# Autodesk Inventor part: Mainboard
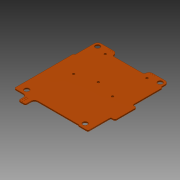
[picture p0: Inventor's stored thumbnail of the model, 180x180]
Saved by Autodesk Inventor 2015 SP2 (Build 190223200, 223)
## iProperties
Created: 2012-08
Part Number: Mainboard
Material: Phenolharz
Document SubType Name: Modeling
Designer: rYan
Mass: 25.8477 g
Surface Area: 244.162 cm^2
Volume: 18.7302 cm^3
Density: 1.38 g/cm^3
Appearance: Glatt - hellorange
Author: rYan
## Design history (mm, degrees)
sketch "Skizze1"
  geometry: L1 (0, 83.325)-(0, -100.704) reference; L2 (-75.98, 0)-(81.98, 0) reference; L3 (-20, -61)-(39, -61); L4 (-25, -66)-(-25, -72); L5 (-27, -74)-(-33, -74); L6 (-35, -72)-(-35, -67); L7 (-40, -62)-(-51, -62); L8 (-53, -60)-(-53, 22); L9 (53, -60)-(53, -31); L10 (55, -29)-(57, -29); L11 (59, -27)-(59, 0); L12 (57, 2)-(55, 2); L13 (53, 4)-(53, 44); L14 (51, 46)-(51, 51); L15 (46, 56)-(28, 56); L16 (21, 49)-(-21, 49); L17 (-51, 24)-(-51, 51); L18 (-46, 56)-(-28, 56); L19 (40, -62)-(51, -62); A1 r 5 centre (-20, -66) between (-20, -61) and (-25, -66); A2 r 2 centre (-27, -72) between (-27, -74) and (-25, -72); A3 r 2 centre (-33, -72) between (-35, -72) and (-33, -74); A4 r 5 centre (-40, -67) between (-35, -67) and (-40, -62); A5 r 2 centre (-51, -60) between (-53, -60) and (-51, -62); A6 r 2 centre (55, -31) between (55, -29) and (53, -31); A7 r 2 centre (57, -27) between (57, -29) and (59, -27); A8 r 2 centre (57, 0) between (59, 0) and (57, 2); A9 r 2 centre (55, 4) between (53, 4) and (55, 2); A10 r 1 centre (52, 44) between (53, 44) and (52, 45); A11 r 1 centre (52, 46) between (51, 46) and (52, 45); A12 r 5 centre (46, 51) between (51, 51) and (46, 56); A13 r 5 centre (28, 51) between (28, 56) and (23, 51); A14 r 2 centre (21, 51) between (21, 49) and (23, 51); A15 r 1 centre (-52, 22) between (-52, 23) and (-53, 22); A16 r 1 centre (-52, 24) between (-52, 23) and (-51, 24); A17 r 5 centre (-46, 51) between (-46, 56) and (-51, 51); A18 r 5 centre (-28, 51) between (-23, 51) and (-28, 56); A19 r 2 centre (-21, 51) between (-23, 51) and (-21, 49); A20 r 0.5 centre (39, -61.5) between (39.5, -61.5) and (39, -61); A21 r 0.5 centre (40, -61.5) between (39.5, -61.5) and (40, -62); A22 r 2 centre (51, -60) between (51, -62) and (53, -60); 1 further point
  constraints: 44 point on circle, 34 end point, 34 tangent, 22 centre point, 9 horizontal, 8 vertical
  dimensions: "d98" = 61 distance between parallel lines of L2 L3; "d99" = 39 distance from line of L3.end L1; "d100" = 20 distance from line of L3.start L1; "d101" = 90 deg dimension on A1.centre L4.start L3.start; "d102" = 5 radius of A1; "d103" = 6 distance of L4.start L4.end; "d104" = 90 deg dimension on A2.centre L5.start L4.end; "d105" = 2 radius of A2; "d106" = 6 distance of L5.start L5.end; "d107" = 90 deg dimension on A3.centre L6.start L5.end; "d108" = 2 radius of A3; "d109" = 5 distance of L6.start L6.end; "d110" = 90 deg dimension on A4.centre L7.start L6.end; "d111" = 5 radius of A4; "d119" = 90 deg dimension on A5.centre L8.start L7.end; "d120" = 2 radius of A5; "d131" = 2 distance of L10.start L10.end; "d132" = 27 distance of L11.start L11.end; "d133" = 2 distance of L12.start L12.end; "d134" = 40 distance of L13.start L13.end; "d135" = 2 radius of A6; "d136" = 2 radius of A9; "d137" = 2 radius of A8; "d138" = 2 radius of A7; "d139" = 5 distance of L14.start L14.end; "d140" = 1 radius of A10; "d141" = 1 radius of A11; "d142" = 0 horizontal distance of A10.centre A11.centre; "d144" = 5 radius of A12; "d145" = 5 radius of A13; "d146" = 90 deg dimension on A13.centre L15.end A13.end; "d148" = 2 radius of A14; "d149" = 1 radius of A15; "d150" = 1 radius of A16; "d151" = 0 horizontal distance of A15.centre A16.centre; "d155" = 5 radius of A17; "d156" = 5 radius of A18; "d184" = 0.5 radius of A20; "d185" = 0.5 radius of A21; "d186" = 1 distance between parallel lines of L19 L3; "d187" = 59 distance between parallel lines of L11 L1; "d188" = 2 distance between parallel lines of L12 L2; "d189" = 2 radius of A22; "d190" = 53 distance between parallel lines of L1 L8; "d191" = 23 distance from line of L2 A15.start; "d192" = 56 distance between parallel lines of L2 L18; "d193" = 2 radius of A19; "d194" = 18 distance of L15.start L15.end; "d195" = 18 distance of L18.start L18.end
extrude "Extrusion1" new body sketch "Skizze1" distance "d11" = 1.6; taper "d12" = 0 deg
sketch "Skizze2"
  geometry: L1 (0, 82)-(0, -100) reference; L2 (-75.4, 0)-(81.4, 0) reference; 4 further points
  constraints: 2 symmetric about line
  dimensions: "d88" = 42 distance from line of L1 point (-42, -55) (= d78); "d89" = 55 distance from line of L2 point (-42, -55) (computed from d79); "d90" = 50 distance from line of L2 point (-45, 50); "d91" = 45 distance from line of L1 point (-45, 50)
hole "Bohrung1" sketch "Skizze2" at (-42, -55), (42, -55), (-45, 50), (45, 50) diameter "d15" = 7; stored, may be unused: countersink angle "d19" = 90 deg, drill point angle "d21" = 118 deg; dims "d16" = 6, "d17" = 4, "d18" = 2, "d20" = 8
sketch "Skizze5"
  geometry: L1 (0, 55.52)-(0, -11.12) reference; L2 (-42, 0)-(42, 0) reference; L3 (-30, 46)-(30, 46); L4 (-28, -1.6)-(28, -1.6); 4 further points
  constraints: 4 end point, 2 coincident, 2 symmetric about line, 1 horizontal, 1 parallel, 1 point on line
  dimensions: "d157" = 6 distance from line of L2 point (0, 6); "d158" = 60 distance of L3.start L3.end; "d159" = 46 distance between parallel lines of L2 L3; "d167" = 56 distance of L4.start L4.end; "d168" = 1.6 distance between parallel lines of L2 L4
hole "Bohrung4" sketch "Skizze5" at (0, 6), (30, 46), (-30, 46), (28, -1.6), (-28, -1.6) diameter "d160" = 3.2; stored, may be unused: countersink angle "d164" = 90 deg, drill point angle "d166" = 118 deg; dims "d161" = 6, "d162" = 4, "d163" = 2, "d165" = 8
sketch "Skizze7"
  geometry: L1 (0, 82)-(0, -100) reference; L2 (-75.4, 0)-(81.4, 0) reference; 2 further points
  dimensions: "d169" = 64.8 distance from line of point (-33.35, -64.8) L2; "d170" = 33.35 distance from line of L1 point (-33.35, -64.8)
hole "Bohrung5" sketch "Skizze7" at (-33.35, -64.8) diameter "d171" = 0.8; stored, may be unused: countersink angle "d175" = 90 deg, drill point angle "d177" = 118 deg; dims "d172" = 6, "d173" = 4, "d174" = 2, "d176" = 8
pattern_linear "Rechteckige Anordnung2" dims "d180" = 2.54, "d183" = 2.54
sketch "Skizze8"
  geometry: L1 (-32.54, 54)-(-27.46, 54); L2 (0, 82)-(0, -100) reference; L3 (-75.4, 0)-(81.4, 0) reference; 2 further points
  constraints: 2 end point, 1 horizontal, 1 midpoint
  dimensions: "d196" = 30 distance from line of L2 point (-30, 54); "d197" = 54 distance from line of L3 point (-30, 54); "d198" = 2.54 distance of point (-30, 54) L1.start; "d199" = 2.54 distance of point (-30, 54) L1.end (derived)
hole "Bohrung6" sketch "Skizze8" at (-30, 54), (-27.46, 54), (-32.54, 54) diameter "d200" = 0.5; stored, may be unused: countersink angle "d204" = 90 deg, drill point angle "d206" = 118 deg; dims "d201" = 6, "d202" = 4, "d203" = 2, "d205" = 8
mirror "Spiegeln1"
node "Volumenkörper1"
other parameters: "d78" = 42, "d79" = 62, "d87" = 64
